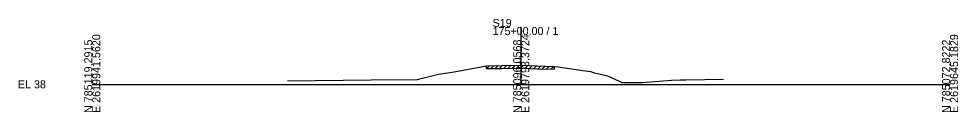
# Model space of a CAD drawing. Extents: x -26 to 1603, y -10 to 5028.
# Drawn here: x -25.7 to 302.8, y -9.7 to 22.8 of the extents above; entities that cross this region are included whole.
import ezdxf

# ---------------------------------------------------------------- set-up
doc = ezdxf.new("R2010")
doc.units = 0
for name, color, linetype in [('RD_GPK_XS_Cell', 7, 'Continuous'), ('RD_XS_ExGround', 7, 'Continuous'), ('RD_XS_ExPaveRet', 7, 'Continuous'), ('RD_XS_TX_Elev_EX', 7, 'Continuous')]:
    doc.layers.add(name, color=color, linetype=linetype)

msp = doc.modelspace()

# ---------------------------------------------------------------- linework, layer by layer
at = {"layer": 'RD_GPK_XS_Cell'}
for p, q in [((150, 0), (150, 19.99)), ((0, 0), (150, 0)), ((150, 0), (300, 0))]:
    msp.add_line(p, q, dxfattribs=at)
at = {"layer": 'RD_XS_ExGround'}
for p, q in [((143.37, 6.54), (150.04, 6.66)), ((150.04, 6.66), (155.58, 6.46)), ((115.52, 2.13), (121.09, 3.5)), ((121.09, 3.5), (126.54, 4.41)), ((126.54, 4.41), (137.89, 6.47)), ((137.89, 6.47), (143.37, 6.54)), ((155.58, 6.46), (161.54, 6.26)), ((161.54, 6.26), (162.95, 6.11)), ((162.95, 6.11), (171.59, 4.81)), ((171.59, 4.81), (174.23, 4.43)), ((174.23, 4.43), (175.66, 4.07)), ((175.66, 4.07), (180.16, 2.95)), ((68.26, 1.25), (97.53, 1.6)), ((97.53, 1.6), (113.7, 1.68)), ((113.7, 1.68), (115.52, 2.13)), ((180.16, 2.95), (184.01, 1.17)), ((184.01, 1.17), (185.24, 0.65)), ((185.24, 0.65), (192.4, 0.65)), ((192.4, 0.65), (202.52, 1.47)), ((202.52, 1.47), (205.7, 1.57)), ((205.7, 1.57), (207.59, 1.56)), ((207.59, 1.56), (220.7, 1.76))]:
    msp.add_line(p, q, dxfattribs=at)
at = {"layer": 'RD_XS_ExPaveRet'}
for p, q in [((145.39, 5.58), (146.41, 6.6)), ((146.89, 5.61), (147.91, 6.62)), ((148.39, 5.63), (149.41, 6.65)), ((149.89, 5.66), (150.86, 6.63)), ((151.39, 5.61), (152.36, 6.58)), ((137.89, 5.47), (138.9, 6.48)), ((137.89, 5.47), (137.89, 6.47)), ((137.89, 5.47), (143.37, 5.54)), ((139.39, 5.49), (140.4, 6.5)), ((140.89, 5.51), (141.9, 6.52)), ((142.39, 5.53), (143.4, 6.54)), ((143.37, 5.54), (150.04, 5.66)), ((143.89, 5.55), (144.91, 6.57)), ((150.04, 5.66), (155.58, 5.46)), ((152.89, 5.56), (153.86, 6.53)), ((154.39, 5.51), (155.36, 6.47)), ((155.58, 5.46), (161.54, 5.26)), ((155.89, 5.45), (156.86, 6.42)), ((157.39, 5.4), (158.36, 6.37)), ((158.89, 5.35), (159.86, 6.31)), ((160.39, 5.3), (161.36, 6.26)), ((161.54, 6.26), (161.54, 5.26))]:
    msp.add_line(p, q, dxfattribs=at)

# ---------------------------------------------------------------- texts
at = {"layer": 'RD_GPK_XS_Cell'}
for s, p in [('S19', (140, 19.99)), ('175+00.00 / 1', (140, 17.19)), ('EL 38', (-26, -1.4))]:
    msp.add_text(s, height=2.8, dxfattribs=at).set_placement(p)
for s, p in [('E 2619941.5620', (2.8, -10)), ('E 2619793.3724', (152.8, -10)), ('E 2619645.1829', (302.8, -10)), ('N 785119.2915', (0, -10)), ('N 785096.0568', (150, -10)), ('N 785072.8222', (300, -10))]:
    msp.add_text(s, height=2.8, rotation=90, dxfattribs=at).set_placement(p)
at = {"layer": 'RD_XS_TX_Elev_EX'}
msp.add_text('44.66', height=0.8, rotation=90, dxfattribs=at).set_placement((149.9, 7.1))

doc.saveas('drawing.dxf')
